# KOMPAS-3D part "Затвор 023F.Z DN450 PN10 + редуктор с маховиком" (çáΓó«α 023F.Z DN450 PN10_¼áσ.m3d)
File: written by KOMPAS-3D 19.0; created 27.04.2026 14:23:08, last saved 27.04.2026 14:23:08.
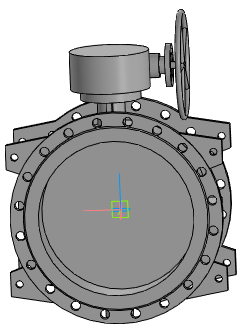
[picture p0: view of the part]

Document properties: Полное имя файла: ..\..\Затвор 023F.Z DN200-DN1600_с маховиком\Затвор 023F.Z DN450 PN10 + редуктор с маховиком.a3d

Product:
- Part/product: Затвор 023F.Z DN450 PN10 + редуктор с маховиком
    Масса: 225.054

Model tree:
1. Операция без истории:1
